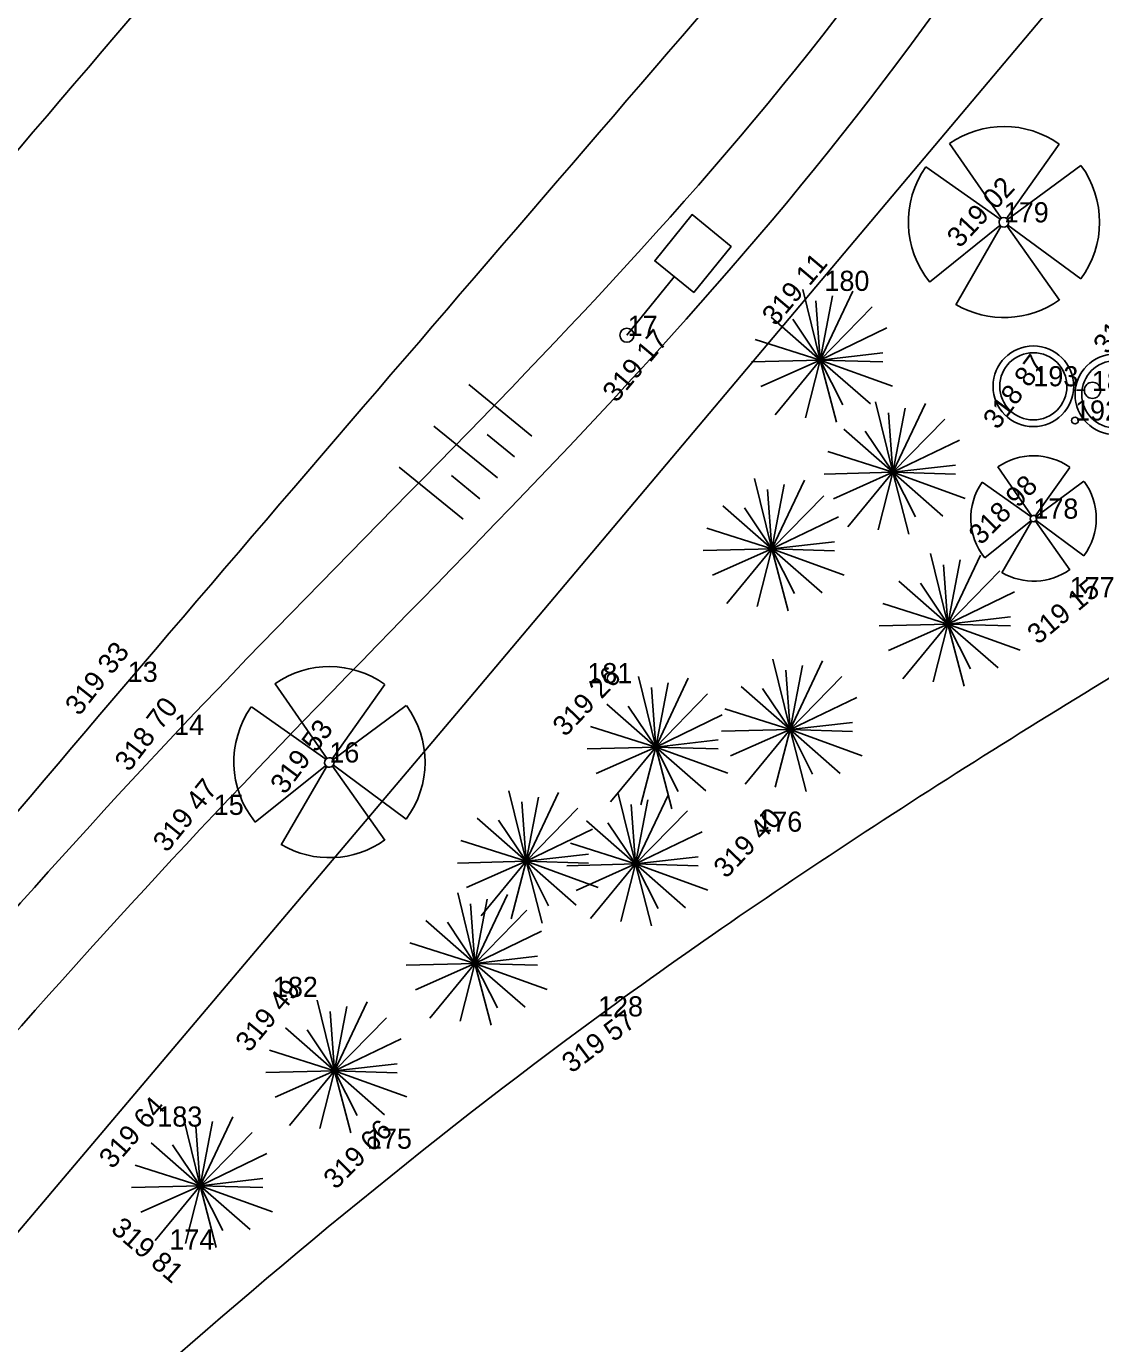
# Model space of a CAD drawing. Extents: x -742884 to -742543, y -1054677 to -1054433.
# Drawn here: x -742753.9 to -742737.91, y -1054520.62 to -1054501.01 of the extents above; entities that cross this region are included whole.
import ezdxf

# ---------------------------------------------------------------- set-up
doc = ezdxf.new("R2010")
doc.units = 0
for name, color, linetype in [('Vrstva 1', 7, 'Continuous'), ('Vrstva 10', 7, 'Continuous'), ('Vrstva 11', 7, 'Continuous'), ('Vrstva 14', 7, 'Continuous'), ('Vrstva 2', 7, 'Continuous'), ('Vrstva 3', 7, 'Continuous'), ('Vrstva 4', 7, 'Continuous'), ('Vrstva 50', 7, 'Continuous'), ('Vrstva 8', 7, 'Continuous')]:
    doc.layers.add(name, color=color, linetype=linetype)

# ---------------------------------------------------------------- blocks, each defined once
blk = doc.blocks.new('Z15')
at = {"layer": 'Vrstva 2'}
for p, q in [((-10, 2), (-8, 6)), ((-10, -2), (-10, 2)), ((-8, 6), (-6, 8)), ((-6, 8), (-2, 10)), ((-2, 10), (2, 10)), ((2, 10), (6, 8)), ((6, 8), (8, 6)), ((8, 6), (10, 2)), ((10, 2), (10, -2)), ((-8, -6), (-10, -2)), ((-6, -8), (-8, -6)), ((-2, -10), (-6, -8)), ((2, -10), (-2, -10)), ((6, -8), (2, -10)), ((8, -6), (6, -8)), ((10, -2), (8, -6))]:
    blk.add_line(p, q, dxfattribs=at)

msp = doc.modelspace()

# ---------------------------------------------------------------- linework, layer by layer
at = {"layer": 'Vrstva 1'}
for p, q in [((-742739.35, -1054503.93), (-742739.35, -1054503.93)), ((-742742.02, -1054504.95), (-742742.02, -1054504.95)), ((-742744.95, -1054505.62), (-742744.95, -1054505.62)), ((-742738.91, -1054506.37), (-742738.91, -1054506.37)), ((-742738.04, -1054506.44), (-742738.04, -1054506.44)), ((-742738.29, -1054506.88), (-742738.29, -1054506.88)), ((-742738.91, -1054508.34), (-742738.91, -1054508.34)), ((-742738.37, -1054509.51), (-742738.37, -1054509.51)), ((-742752.39, -1054510.77), (-742752.39, -1054510.77)), ((-742745.55, -1054510.79), (-742745.55, -1054510.79)), ((-742751.7, -1054511.56), (-742751.7, -1054511.56)), ((-742749.39, -1054511.97), (-742749.39, -1054511.97)), ((-742751.11, -1054512.75), (-742751.11, -1054512.75)), ((-742743.02, -1054513), (-742743.02, -1054513)), ((-742750.23, -1054515.46), (-742750.23, -1054515.46)), ((-742745.39, -1054515.75), (-742745.39, -1054515.75)), ((-742751.95, -1054517.39), (-742751.95, -1054517.39)), ((-742748.83, -1054517.72), (-742748.83, -1054517.72)), ((-742751.77, -1054519.22), (-742751.77, -1054519.22))]:
    msp.add_line(p, q, dxfattribs=at)
at = {"layer": 'Vrstva 10'}
for p, q in [((-742739.383, -1054503.873), (-742740.158, -1054502.757)), ((-742739.309, -1054503.873), (-742738.524, -1054502.767)), ((-742739.404, -1054503.881), (-742740.51, -1054503.103)), ((-742739.297, -1054503.889), (-742738.205, -1054503.081)), ((-742739.407, -1054503.978), (-742740.455, -1054504.82)), ((-742739.393, -1054503.992), (-742740.066, -1054505.156)), ((-742739.302, -1054503.987), (-742738.522, -1054505.086)), ((-742739.29, -1054503.971), (-742738.205, -1054504.772)), ((-742742.082, -1054505.98), (-742742.339, -1054504.93)), ((-742742.082, -1054505.98), (-742741.597, -1054504.955)), ((-742742.082, -1054505.98), (-742742.146, -1054505.096)), ((-742742.082, -1054505.98), (-742741.898, -1054505.024)), ((-742742.082, -1054505.98), (-742741.309, -1054505.189)), ((-742742.082, -1054505.98), (-742742.811, -1054505.34)), ((-742742.082, -1054505.98), (-742742.492, -1054505.369)), ((-742742.082, -1054505.98), (-742741.09, -1054505.501)), ((-742742.082, -1054505.98), (-742743.051, -1054505.673)), ((-742742.086, -1054505.974), (-742742.086, -1054505.974)), ((-742742.082, -1054505.98), (-742741.15, -1054505.874)), ((-742742.082, -1054505.98), (-742743.104, -1054506.006)), ((-742742.082, -1054505.98), (-742742.967, -1054506.373)), ((-742742.082, -1054505.98), (-742742.752, -1054506.794)), ((-742742.082, -1054505.98), (-742742.302, -1054506.839)), ((-742742.082, -1054505.98), (-742742.082, -1054505.98)), ((-742742.082, -1054505.98), (-742741.746, -1054506.644)), ((-742742.082, -1054505.98), (-742741.007, -1054506.369)), ((-742742.082, -1054505.98), (-742741.15, -1054506.008)), ((-742742.082, -1054505.98), (-742741.336, -1054506.633)), ((-742742.082, -1054505.98), (-742741.842, -1054506.902)), ((-742742.082, -1054505.98), (-742742.082, -1054505.98)), ((-742741.002, -1054507.65), (-742741.259, -1054506.6)), ((-742741.002, -1054507.65), (-742740.517, -1054506.625)), ((-742741.002, -1054507.65), (-742740.818, -1054506.694)), ((-742741.002, -1054507.65), (-742741.066, -1054506.766)), ((-742741.002, -1054507.65), (-742740.229, -1054506.859)), ((-742741.002, -1054507.65), (-742741.731, -1054507.01)), ((-742741.002, -1054507.65), (-742741.412, -1054507.039)), ((-742741.002, -1054507.65), (-742741.971, -1054507.343)), ((-742741.002, -1054507.65), (-742740.01, -1054507.171)), ((-742741.002, -1054507.65), (-742740.07, -1054507.544)), ((-742742.802, -1054508.79), (-742743.059, -1054507.74)), ((-742741.002, -1054507.65), (-742742.024, -1054507.676)), ((-742741.002, -1054507.65), (-742741.887, -1054508.043)), ((-742741.002, -1054507.65), (-742741.672, -1054508.464)), ((-742741.002, -1054507.65), (-742741.222, -1054508.509)), ((-742741.006, -1054507.644), (-742741.006, -1054507.644)), ((-742741.002, -1054507.65), (-742741.002, -1054507.65)), ((-742741.002, -1054507.65), (-742740.666, -1054508.314)), ((-742741.002, -1054507.65), (-742739.927, -1054508.039)), ((-742741.002, -1054507.65), (-742740.07, -1054507.678)), ((-742741.002, -1054507.65), (-742740.256, -1054508.303)), ((-742741.002, -1054507.65), (-742740.762, -1054508.572)), ((-742741.002, -1054507.65), (-742741.002, -1054507.65)), ((-742738.932, -1054508.303), (-742739.44, -1054507.571)), ((-742738.883, -1054508.303), (-742738.368, -1054507.577)), ((-742742.802, -1054508.79), (-742742.866, -1054507.906)), ((-742742.802, -1054508.79), (-742742.317, -1054507.765)), ((-742742.802, -1054508.79), (-742742.618, -1054507.834)), ((-742738.946, -1054508.309), (-742739.67, -1054507.798)), ((-742738.875, -1054508.314), (-742738.159, -1054507.784)), ((-742742.802, -1054508.79), (-742742.029, -1054507.999)), ((-742742.802, -1054508.79), (-742743.531, -1054508.15)), ((-742742.802, -1054508.79), (-742743.212, -1054508.179)), ((-742742.802, -1054508.79), (-742741.81, -1054508.311)), ((-742742.802, -1054508.79), (-742743.771, -1054508.483)), ((-742738.947, -1054508.371), (-742739.634, -1054508.924)), ((-742738.939, -1054508.381), (-742739.379, -1054509.145)), ((-742738.878, -1054508.378), (-742738.366, -1054509.1)), ((-742738.87, -1054508.367), (-742738.159, -1054508.893)), ((-742742.802, -1054508.79), (-742741.87, -1054508.684)), ((-742742.802, -1054508.79), (-742743.824, -1054508.816)), ((-742742.802, -1054508.79), (-742743.687, -1054509.183)), ((-742742.802, -1054508.79), (-742743.472, -1054509.604)), ((-742742.802, -1054508.79), (-742743.022, -1054509.649)), ((-742742.806, -1054508.784), (-742742.806, -1054508.784)), ((-742742.802, -1054508.79), (-742742.802, -1054508.79)), ((-742742.802, -1054508.79), (-742742.466, -1054509.454)), ((-742742.802, -1054508.79), (-742741.727, -1054509.179)), ((-742742.802, -1054508.79), (-742741.87, -1054508.818)), ((-742742.802, -1054508.79), (-742742.056, -1054509.443)), ((-742742.802, -1054508.79), (-742742.562, -1054509.712)), ((-742742.802, -1054508.79), (-742742.802, -1054508.79)), ((-742740.182, -1054509.91), (-742740.439, -1054508.86)), ((-742740.182, -1054509.91), (-742739.697, -1054508.885)), ((-742740.182, -1054509.91), (-742740.246, -1054509.026)), ((-742740.182, -1054509.91), (-742739.998, -1054508.954)), ((-742740.182, -1054509.91), (-742740.911, -1054509.27)), ((-742740.182, -1054509.91), (-742740.592, -1054509.299)), ((-742740.182, -1054509.91), (-742739.409, -1054509.119)), ((-742740.182, -1054509.91), (-742739.19, -1054509.431)), ((-742740.182, -1054509.91), (-742741.151, -1054509.603)), ((-742740.182, -1054509.91), (-742739.25, -1054509.804)), ((-742740.182, -1054509.91), (-742741.204, -1054509.936)), ((-742740.182, -1054509.91), (-742741.067, -1054510.303)), ((-742740.182, -1054509.91), (-742740.852, -1054510.724)), ((-742740.182, -1054509.91), (-742740.402, -1054510.769)), ((-742740.186, -1054509.904), (-742740.186, -1054509.904)), ((-742740.182, -1054509.91), (-742740.182, -1054509.91)), ((-742740.182, -1054509.91), (-742739.846, -1054510.574)), ((-742740.182, -1054509.91), (-742739.107, -1054510.299)), ((-742740.182, -1054509.91), (-742739.25, -1054509.938)), ((-742740.182, -1054509.91), (-742739.436, -1054510.563)), ((-742740.182, -1054509.91), (-742739.942, -1054510.832)), ((-742740.182, -1054509.91), (-742740.182, -1054509.91)), ((-742742.532, -1054511.48), (-742742.789, -1054510.43)), ((-742742.532, -1054511.48), (-742742.047, -1054510.455)), ((-742742.532, -1054511.48), (-742742.596, -1054510.596)), ((-742742.532, -1054511.48), (-742742.348, -1054510.524)), ((-742749.423, -1054511.913), (-742750.198, -1054510.797)), ((-742749.349, -1054511.913), (-742748.564, -1054510.807)), ((-742744.532, -1054511.74), (-742744.789, -1054510.69)), ((-742744.532, -1054511.74), (-742744.596, -1054510.856)), ((-742744.532, -1054511.74), (-742744.047, -1054510.715)), ((-742744.532, -1054511.74), (-742744.348, -1054510.784)), ((-742742.532, -1054511.48), (-742743.261, -1054510.84)), ((-742742.532, -1054511.48), (-742742.942, -1054510.869)), ((-742742.532, -1054511.48), (-742741.759, -1054510.689)), ((-742744.532, -1054511.74), (-742743.759, -1054510.949)), ((-742742.532, -1054511.48), (-742741.54, -1054511.001)), ((-742749.444, -1054511.921), (-742750.55, -1054511.143)), ((-742749.337, -1054511.929), (-742748.245, -1054511.121)), ((-742744.532, -1054511.74), (-742745.261, -1054511.1)), ((-742744.532, -1054511.74), (-742744.942, -1054511.129)), ((-742744.532, -1054511.74), (-742743.54, -1054511.261)), ((-742742.532, -1054511.48), (-742743.501, -1054511.173)), ((-742744.532, -1054511.74), (-742745.501, -1054511.433)), ((-742742.532, -1054511.48), (-742741.6, -1054511.374)), ((-742744.532, -1054511.74), (-742743.6, -1054511.634)), ((-742742.532, -1054511.48), (-742743.554, -1054511.506)), ((-742742.532, -1054511.48), (-742743.417, -1054511.873)), ((-742742.532, -1054511.48), (-742743.202, -1054512.294)), ((-742742.532, -1054511.48), (-742742.752, -1054512.339)), ((-742742.536, -1054511.474), (-742742.536, -1054511.474)), ((-742742.532, -1054511.48), (-742742.532, -1054511.48)), ((-742742.532, -1054511.48), (-742742.196, -1054512.144)), ((-742742.532, -1054511.48), (-742741.457, -1054511.869)), ((-742742.532, -1054511.48), (-742741.6, -1054511.508)), ((-742742.532, -1054511.48), (-742741.786, -1054512.133)), ((-742742.532, -1054511.48), (-742742.292, -1054512.402)), ((-742742.532, -1054511.48), (-742742.532, -1054511.48)), ((-742744.532, -1054511.74), (-742745.554, -1054511.766)), ((-742744.532, -1054511.74), (-742745.417, -1054512.133)), ((-742744.532, -1054511.74), (-742745.202, -1054512.554)), ((-742744.532, -1054511.74), (-742744.752, -1054512.599)), ((-742744.536, -1054511.734), (-742744.536, -1054511.734)), ((-742744.532, -1054511.74), (-742744.532, -1054511.74)), ((-742744.532, -1054511.74), (-742744.196, -1054512.404)), ((-742744.532, -1054511.74), (-742743.457, -1054512.129)), ((-742744.532, -1054511.74), (-742743.6, -1054511.768)), ((-742744.532, -1054511.74), (-742743.786, -1054512.393)), ((-742744.532, -1054511.74), (-742744.292, -1054512.662)), ((-742744.532, -1054511.74), (-742744.532, -1054511.74)), ((-742749.447, -1054512.018), (-742750.495, -1054512.86)), ((-742749.433, -1054512.032), (-742750.106, -1054513.196)), ((-742749.342, -1054512.027), (-742748.562, -1054513.126)), ((-742749.33, -1054512.011), (-742748.245, -1054512.812)), ((-742746.462, -1054513.44), (-742746.719, -1054512.39)), ((-742746.462, -1054513.44), (-742745.977, -1054512.415)), ((-742744.832, -1054513.48), (-742745.089, -1054512.43)), ((-742746.462, -1054513.44), (-742746.526, -1054512.556)), ((-742746.462, -1054513.44), (-742746.278, -1054512.484)), ((-742744.832, -1054513.48), (-742744.896, -1054512.596)), ((-742744.832, -1054513.48), (-742744.347, -1054512.455)), ((-742744.832, -1054513.48), (-742744.648, -1054512.524)), ((-742746.462, -1054513.44), (-742747.191, -1054512.8)), ((-742746.462, -1054513.44), (-742746.872, -1054512.829)), ((-742746.462, -1054513.44), (-742745.689, -1054512.649)), ((-742744.832, -1054513.48), (-742745.561, -1054512.84)), ((-742744.832, -1054513.48), (-742744.059, -1054512.689)), ((-742746.462, -1054513.44), (-742745.47, -1054512.961)), ((-742744.832, -1054513.48), (-742745.242, -1054512.869)), ((-742744.832, -1054513.48), (-742743.84, -1054513.001)), ((-742746.462, -1054513.44), (-742747.431, -1054513.133)), ((-742744.832, -1054513.48), (-742745.801, -1054513.173)), ((-742746.462, -1054513.44), (-742745.53, -1054513.334)), ((-742744.832, -1054513.48), (-742743.9, -1054513.374)), ((-742746.462, -1054513.44), (-742747.484, -1054513.466)), ((-742746.462, -1054513.44), (-742747.347, -1054513.833)), ((-742746.462, -1054513.44), (-742747.132, -1054514.254)), ((-742746.462, -1054513.44), (-742746.682, -1054514.299)), ((-742746.466, -1054513.434), (-742746.466, -1054513.434)), ((-742746.462, -1054513.44), (-742746.462, -1054513.44)), ((-742746.462, -1054513.44), (-742746.126, -1054514.104)), ((-742746.462, -1054513.44), (-742745.387, -1054513.829)), ((-742746.462, -1054513.44), (-742745.53, -1054513.468)), ((-742746.462, -1054513.44), (-742745.716, -1054514.093)), ((-742746.462, -1054513.44), (-742746.222, -1054514.362)), ((-742746.462, -1054513.44), (-742746.462, -1054513.44)), ((-742744.832, -1054513.48), (-742745.854, -1054513.506)), ((-742744.832, -1054513.48), (-742745.717, -1054513.873)), ((-742744.832, -1054513.48), (-742745.502, -1054514.294)), ((-742744.832, -1054513.48), (-742745.052, -1054514.339)), ((-742744.836, -1054513.474), (-742744.836, -1054513.474)), ((-742744.832, -1054513.48), (-742744.832, -1054513.48)), ((-742744.832, -1054513.48), (-742744.496, -1054514.144)), ((-742744.832, -1054513.48), (-742743.757, -1054513.869)), ((-742744.832, -1054513.48), (-742743.9, -1054513.508)), ((-742744.832, -1054513.48), (-742744.086, -1054514.133)), ((-742744.832, -1054513.48), (-742744.592, -1054514.402)), ((-742744.832, -1054513.48), (-742744.832, -1054513.48)), ((-742747.222, -1054514.96), (-742747.479, -1054513.91)), ((-742747.222, -1054514.96), (-742746.737, -1054513.935)), ((-742747.222, -1054514.96), (-742747.038, -1054514.004)), ((-742747.222, -1054514.96), (-742747.286, -1054514.076)), ((-742747.222, -1054514.96), (-742746.449, -1054514.169)), ((-742747.222, -1054514.96), (-742747.951, -1054514.32)), ((-742747.222, -1054514.96), (-742747.632, -1054514.349)), ((-742747.222, -1054514.96), (-742746.23, -1054514.481)), ((-742747.222, -1054514.96), (-742748.191, -1054514.653)), ((-742747.222, -1054514.96), (-742748.244, -1054514.986)), ((-742747.222, -1054514.96), (-742748.107, -1054515.353)), ((-742747.222, -1054514.96), (-742747.892, -1054515.774)), ((-742747.222, -1054514.96), (-742747.442, -1054515.819)), ((-742747.226, -1054514.954), (-742747.226, -1054514.954)), ((-742747.222, -1054514.96), (-742746.29, -1054514.854)), ((-742747.222, -1054514.96), (-742747.222, -1054514.96)), ((-742747.222, -1054514.96), (-742746.886, -1054515.624)), ((-742747.222, -1054514.96), (-742746.147, -1054515.349)), ((-742747.222, -1054514.96), (-742746.29, -1054514.988)), ((-742747.222, -1054514.96), (-742746.476, -1054515.613)), ((-742747.222, -1054514.96), (-742746.982, -1054515.882)), ((-742747.222, -1054514.96), (-742747.222, -1054514.96)), ((-742749.312, -1054516.56), (-742749.569, -1054515.51)), ((-742749.312, -1054516.56), (-742748.827, -1054515.535)), ((-742749.312, -1054516.56), (-742749.376, -1054515.676)), ((-742749.312, -1054516.56), (-742749.128, -1054515.604)), ((-742749.312, -1054516.56), (-742748.539, -1054515.769)), ((-742749.312, -1054516.56), (-742750.041, -1054515.92)), ((-742749.312, -1054516.56), (-742749.722, -1054515.949)), ((-742749.312, -1054516.56), (-742748.32, -1054516.081)), ((-742749.312, -1054516.56), (-742750.281, -1054516.253)), ((-742749.312, -1054516.56), (-742750.334, -1054516.586)), ((-742749.312, -1054516.56), (-742750.197, -1054516.953)), ((-742749.312, -1054516.56), (-742749.982, -1054517.374)), ((-742749.312, -1054516.56), (-742749.532, -1054517.419)), ((-742749.316, -1054516.554), (-742749.316, -1054516.554)), ((-742749.312, -1054516.56), (-742748.38, -1054516.454)), ((-742749.312, -1054516.56), (-742749.312, -1054516.56)), ((-742749.312, -1054516.56), (-742748.976, -1054517.224)), ((-742749.312, -1054516.56), (-742748.237, -1054516.949)), ((-742749.312, -1054516.56), (-742748.38, -1054516.588)), ((-742749.312, -1054516.56), (-742748.566, -1054517.213)), ((-742749.312, -1054516.56), (-742749.072, -1054517.482)), ((-742749.312, -1054516.56), (-742749.312, -1054516.56)), ((-742751.312, -1054518.27), (-742751.569, -1054517.22)), ((-742751.312, -1054518.27), (-742750.827, -1054517.245)), ((-742751.312, -1054518.27), (-742751.128, -1054517.314)), ((-742751.312, -1054518.27), (-742751.376, -1054517.386)), ((-742751.312, -1054518.27), (-742750.539, -1054517.479)), ((-742751.312, -1054518.27), (-742752.041, -1054517.63)), ((-742751.312, -1054518.27), (-742751.722, -1054517.659)), ((-742751.312, -1054518.27), (-742750.32, -1054517.791)), ((-742751.312, -1054518.27), (-742752.281, -1054517.963)), ((-742751.312, -1054518.27), (-742752.334, -1054518.296)), ((-742751.312, -1054518.27), (-742752.197, -1054518.663)), ((-742751.312, -1054518.27), (-742751.982, -1054519.084)), ((-742751.312, -1054518.27), (-742751.532, -1054519.129)), ((-742751.316, -1054518.264), (-742751.316, -1054518.264)), ((-742751.312, -1054518.27), (-742750.38, -1054518.164)), ((-742751.312, -1054518.27), (-742751.312, -1054518.27)), ((-742751.312, -1054518.27), (-742750.976, -1054518.934)), ((-742751.312, -1054518.27), (-742750.237, -1054518.659)), ((-742751.312, -1054518.27), (-742750.38, -1054518.298)), ((-742751.312, -1054518.27), (-742750.566, -1054518.923)), ((-742751.312, -1054518.27), (-742751.072, -1054519.192)), ((-742751.312, -1054518.27), (-742751.312, -1054518.27))]:
    msp.add_line(p, q, dxfattribs=at)
for centre, radius, start, end in [((-742739.347, -1054503.925), 1.422, 54.7465, 124.8105), ((-742739.348, -1054503.922), 1.423, 144.8767, 218.9336), ((-742739.347, -1054503.925), 1.422, 323.4756, 36.2971), ((-742739.347, -1054503.925), 1.422, 239.6151, 305.4552), ((-742738.907, -1054508.337), 0.933, 54.7465, 124.8105), ((-742738.908, -1054508.335), 0.933, 144.8767, 218.9336), ((-742738.907, -1054508.337), 0.933, 323.4756, 36.2971), ((-742738.907, -1054508.337), 0.933, 239.6151, 305.4552), ((-742749.387, -1054511.965), 1.422, 54.7465, 124.8105), ((-742749.388, -1054511.962), 1.423, 144.8767, 218.9336), ((-742749.387, -1054511.965), 1.422, 323.4756, 36.2971), ((-742749.387, -1054511.965), 1.422, 239.6151, 305.4552)]:
    msp.add_arc(centre, radius, start, end, dxfattribs=at)
at = {"layer": 'Vrstva 11'}
for p, q in [((-742746.374, -1054507.111), (-742747.314, -1054506.344)), ((-742746.888, -1054507.732), (-742747.835, -1054506.964)), ((-742746.631, -1054507.422), (-742747.041, -1054507.088)), ((-742748.348, -1054507.574), (-742747.399, -1054508.347)), ((-742747.572, -1054507.699), (-742747.147, -1054508.044))]:
    msp.add_line(p, q, dxfattribs=at)
for points in [[(-742777.63, -1054542.12), (-742764.61, -1054526.83), (-742751.7, -1054511.56), (-742738.47, -1054495.82), (-742727.02, -1054482.18), (-742726.38, -1054482.19), (-742725.15, -1054482.94)], [(-742776.7, -1054542.68), (-742764.01, -1054527.79), (-742751.11, -1054512.75), (-742737.61, -1054496.47), (-742726.42, -1054483.98), (-742725.9, -1054484.03), (-742714, -1054491.86), (-742704.819, -1054497.481), (-742700.94, -1054500.269), (-742696.44, -1054503.39), (-742688.83, -1054509.5), (-742682.54, -1054514.17), (-742675.15, -1054519.77), (-742673.01, -1054522.11), (-742671.05, -1054524.7)], [(-742641.45, -1054542), (-742646.08, -1054542.32), (-742650.28, -1054545.1), (-742653.63, -1054549.14), (-742658.66, -1054557.13), (-742664.13, -1054565.84), (-742667.81, -1054569.62), (-742669.76, -1054570.07), (-742674.4, -1054567.88), (-742684.66, -1054562.03), (-742693.02, -1054556.88), (-742694.43, -1054554.37), (-742693.99, -1054552.67), (-742684.52, -1054539.64), (-742677.51, -1054529.95), (-742676.26, -1054526.54), (-742677.27, -1054522.39), (-742681.19, -1054517.29), (-742689.28, -1054510.73), (-742697.86, -1054505.14), (-742704.02, -1054502.75), (-742713.11, -1054501.07), (-742723.98, -1054503.51), (-742736.77, -1054510.1), (-742745.39, -1054515.75), (-742752.81, -1054521.82), (-742762.72, -1054531.38), (-742770.54, -1054539.36), (-742775.54, -1054544.64)]]:
    msp.add_spline(points, degree=3, dxfattribs=at)
at = {"layer": 'Vrstva 14'}
msp.add_line((-742744.96, -1054505.609), (-742744.256, -1054504.739), dxfattribs=at)
msp.add_lwpolyline([(-742743.966, -1054504.974), (-742744.545, -1054504.503), (-742743.989, -1054503.815), (-742743.41, -1054504.291)], close=True, dxfattribs=at)
msp.add_circle((-742744.961, -1054505.61), 0.105, dxfattribs=at)
at = {"layer": 'Vrstva 4'}
for points in [[(-742783.23, -1054536.93), (-742770.7, -1054522.44), (-742757.28, -1054506.67), (-742744.15, -1054491.3), (-742731.95, -1054477.03), (-742724.73, -1054468.59)], [(-742778.49, -1054541.37), (-742765.63, -1054526.43), (-742752.39, -1054510.77), (-742739.19, -1054495.37), (-742727.3, -1054481.14)]]:
    msp.add_spline(points, degree=3, dxfattribs=at)
at = {"layer": 'Vrstva 50'}
msp.add_lwpolyline([(-742724.95, -1054484.46), (-742747.39, -1054511.11), (-742766.3, -1054533.47), (-742786.45, -1054556.28), (-742796.57, -1054568.72)], dxfattribs=at)
at = {"layer": 'Vrstva 8'}
msp.add_line((-742738.151, -1054506.429), (-742738.266, -1054506.427), dxfattribs=at)
for centre, radius in [((-742738.91, -1054506.37), 0.6), ((-742738.91, -1054506.37), 0.5), ((-742737.69, -1054506.49), 0.6), ((-742737.69, -1054506.49), 0.5), ((-742738.03, -1054506.43), 0.121), ((-742738.29, -1054506.88), 0.05)]:
    msp.add_circle(centre, radius, dxfattribs=at)

# ---------------------------------------------------------------- block references
at = {"layer": 'Vrstva 10', "rotation": -30.671756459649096}
for p, xscale, yscale in [((-742739.35, -1054503.93), 0.00710900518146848, 0.007109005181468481), ((-742738.91, -1054508.34), 0.00466421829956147, 0.00466421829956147), ((-742749.39, -1054511.97), 0.00710900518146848, 0.007109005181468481)]:
    msp.add_blockref('Z15', p, dxfattribs=dict(at, xscale=xscale, yscale=yscale))

# ---------------------------------------------------------------- texts
at = {"layer": 'Vrstva 2'}
for s, p in [('179', (-742739.35, -1054503.93)), ('180', (-742742.02, -1054504.95)), ('17', (-742744.95, -1054505.62)), ('193', (-742738.91, -1054506.37)), ('186', (-742738.04, -1054506.44)), ('192', (-742738.29, -1054506.88)), ('178', (-742738.91, -1054508.34)), ('177', (-742738.37, -1054509.51)), ('13', (-742752.39, -1054510.77)), ('181', (-742745.55, -1054510.79)), ('14', (-742751.7, -1054511.56)), ('16', (-742749.39, -1054511.97)), ('15', (-742751.11, -1054512.75)), ('176', (-742743.02, -1054513)), ('182', (-742750.23, -1054515.46)), ('128', (-742745.39, -1054515.75)), ('183', (-742751.95, -1054517.39)), ('175', (-742748.83, -1054517.72)), ('174', (-742751.77, -1054519.22))]:
    msp.add_text(s, height=0.3, dxfattribs=at).set_placement(p)
at = {"layer": 'Vrstva 3'}
for s, rotation, p in [('319 02 ', 46.8841, (-742740.006, -1054504.324)), ('319 11 ', 49.8389, (-742742.747, -1054505.486)), ('318 83 ', 53.3787, (-742737.803, -1054505.908)), ('319 17 ', 49.8769, (-742745.12, -1054506.626)), ('318 87 ', 53.3787, (-742739.443, -1054507.028)), ('318 98 ', 45.2525, (-742739.689, -1054508.745)), ('319 15 ', 39.688, (-742738.843, -1054510.225)), ('319 33 ', 51.6468, (-742753.113, -1054511.289)), ('319 26 ', 46.2018, (-742745.879, -1054511.599)), ('318 70 ', 52.6049, (-742752.371, -1054512.121)), ('319 53 ', 53.3374, (-742750.052, -1054512.459)), ('319 47 ', 51.0333, (-742751.808, -1054513.322)), ('319 40 ', 46.2364, (-742743.484, -1054513.709)), ('319 49 ', 50.4119, (-742750.582, -1054516.299)), ('319 57 ', 36.7218, (-742745.785, -1054516.605)), ('319 64 ', 48.8141, (-742752.62, -1054518.034)), ('319 66 ', 45.4063, (-742749.294, -1054518.339)), ('319 81 ', 319.4376, (-742752.657, -1054518.941))]:
    msp.add_text(s, height=0.3, rotation=rotation, dxfattribs=at).set_placement(p)

doc.saveas('drawing.dxf')
